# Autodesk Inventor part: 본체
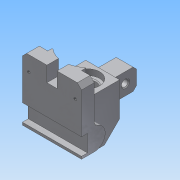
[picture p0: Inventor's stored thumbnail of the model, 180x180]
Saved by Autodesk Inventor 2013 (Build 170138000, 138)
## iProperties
Created: 2016-11
Part Number: 본체
Material: 알루미늄 6061
Document SubType Name: Modeling
Designer: Administrator
Density: 2.71 g/cm^3
Mass: 470.387 g
Surface Area: 316.229 cm^2
Volume: 173.574 cm^3
Author: Administrator
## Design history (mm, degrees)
sketch "스케치4"
  geometry: L1 (18, -11)-(0, -29); L2 (0, -29)-(-26, -29); L3 (-30, -25)-(-30, 29); L4 (-30, 29)-(18, 29); L5 (18, 29)-(18, -11); L6 (0, -29)-(0, 29); L7 (-26, -29)-(-30, -25); 3 further points
  constraints: 14 end point, 3 point on line, 2 vertical, 1 coincident, 1 horizontal, 1 midpoint, 1 parallel, 1 perpendicular
  dimensions: "d4" = 45 deg angle of L2 L1; "d5" = 58 distance between parallel lines of L2 L4; "d6" = 48 distance between parallel lines of L3 L5; "d8" = 30 distance from line of L3 L1.end; "d9" = 4 distance of L2.end point (-30, -29); "d10" = 4 distance of L3.start point (-30, -29) (= d9)
extrude "돌출1" new body sketch "스케치4" stored distance "d11" = 40; taper "d12" = 0 deg
sketch "스케치5"
  geometry: L1 (18, 29)-(18, -11) reference; L2 (18, -11)-(0, -29) reference; L3 (0, -29)-(-26, -29) reference; L4 (-26, -29)-(-30, -25) reference; L5 (-30, -25)-(-30, 29) reference; L6 (-30, 29)-(18, 29) reference; L7 (-27, -15)-(-42, -15); L8 (-42, 61)-(-27, 61); L9 (-27, 15.292)-(-27, 61); L10 (-35, -12)-(-42, -12); L11 (-35, -12)-(-35, 8); L12 (-35, 8)-(-42, 8); L13 (-42, -15)-(-42, -12); L14 (-42, 8)-(-42, 61); A1 r 13 centre (-27, -2) between (-27, -15) and (-23.389, 10.488); A2 r 5 centre (-22, 15.292) between (-27, 15.292) and (-23.389, 10.488); 2 further points
  constraints: 16 end point, 5 point on circle, 4 perpendicular, 3 point on line, 3 tangent, 2 centre point, 2 parallel, 1 horizontal
  dimensions: "d19" = 90 distance between parallel lines of L8 L3; "d21" = 26 diameter of A1; "d22" = 63 distance from line of L8 A1.centre; "d23" = 3 distance between parallel lines of L7 L10; "d25" = 20 distance of L10.start L11.end; "d26" = 60 distance between parallel lines of L1 L14; "d27" = 15 distance between parallel lines of L14 L9; "d28" = 7 distance between parallel lines of L13 L11; "d29" = 5 radius of A2
extrude "돌출2" join sketch "스케치5" stored distance "d30" = 70; taper "d31" = 0 deg
sketch "스케치6"
  geometry: L1 (0, -45)-(40, -45) reference; L2 (0, -45)-(0, 0) reference; L3 (0, -40)-(40, -40); L4 (40, -40)-(40, -45); L5 (40, -45)-(0, -45); L6 (0, -45)-(0, -40); 2 further points
  constraints: 8 end point, 2 midpoint, 2 parallel, 1 collinear, 1 horizontal, 1 perpendicular
  dimensions: "d32" = 5 distance of L5.end L3.start
extrude "돌출3" join sketch "스케치6" stored distance "d34" = 10; taper "d35" = 0 deg
sketch "스케치7"
  geometry: L1 (0, 0)-(70, 0) reference; L2 (0, 0)-(0, 15) reference; L3 (0, 15)-(15, 15) reference; L4 (15, 15)-(15, 20) reference; L5 (15, 20)-(55, 20) reference; L6 (55, 20)-(55, 15) reference; L7 (55, 15)-(70, 15) reference; L8 (70, 15)-(70, 0) reference; L9 (70, 0)-(0, 0) reference; C1 r 29 at (35, 42); 2 further points
  constraints: 1 centre point, 1 midpoint, 1 vertical alignment
  dimensions: "d36" = 58 diameter of C1; "d37" = 42 distance from line of L1 C1.centre
extrude "돌출4" cut sketch "스케치7" distance "d38" = 18; taper "d39" = 0 deg
sketch "스케치8"
  geometry: L1 (0, -29)-(-26, -29) reference; L2 (-26, -29)-(-30, -25) reference; L3 (-30, -25)-(-30, -15) reference; L4 (-30, -15)-(-42, -15) reference; L5 (-42, -15)-(-42, -12) reference; L6 (-42, -12)-(-35, -12) reference; L7 (-35, -12)-(-35, 8) reference; L8 (-35, 8)-(-42, 8) reference; L9 (-42, 8)-(-42, 61) reference; L10 (-42, 61)-(-29, 61) reference; L11 (-29, 61)-(-29, 43) reference; L12 (-29, 43)-(-22, 43) reference; L13 (-22, 43)-(-22, 29) reference; L14 (-22, 29)-(18, 29) reference; L15 (18, 29)-(18, -11) reference; L16 (18, -11)-(0, -29) reference; L17 (18, 24)-(44, 24); L18 (48, 20)-(48, 3); L19 (44, -1)-(18, -1); L20 (44, 24)-(48, 20); L21 (48, 3)-(44, -1); 3 further points
  constraints: 10 end point, 6 point on line, 1 horizontal, 1 parallel, 1 perpendicular
  dimensions: "d40" = 25 distance between parallel lines of L19 L17; "d42" = 5 distance between parallel lines of L17 L14; "d43" = 4 distance of L17.end point (48, 24); "d44" = 4 distance of L18.start point (48, 24) (= d43); "d45" = 4 distance of L18.end point (48, -1) (= d43); "d46" = 4 distance of L19.start point (48, -1) (= d45); "d47" = 90 distance between parallel lines of L18 L9
extrude "돌출5" join sketch "스케치8" stored distance "d48" = 20; taper "d49" = 0 deg
sketch "스케치9"
  geometry: L1 (-24, 44)-(-24, 18) reference; L2 (-61, -42)-(-8, -42) reference; 2 further points
  dimensions: "d50" = 12.5 distance from line of point (-11.5, 35) L1; "d51" = 77 distance from line of L2 point (-11.5, 35)
hole "구멍1" sketch "스케치9" at (-11.5, 35) diameter "d52" = 8; stored, may be unused: countersink angle "d56" = 90 deg, drill point angle "d58" = 118 deg; dims "d53" = 6, "d54" = 4, "d55" = 2, "d57" = 8
sketch "스케치12"
  geometry: 2 further points
  constraints: 1 coincident
hole "구멍2" sketch "스케치12" at (20, -18) diameter "d60" = 20; stored, may be unused: countersink angle "d64" = 90 deg, drill point angle "d66" = 118 deg; dims "d61" = 6, "d62" = 29, "d63" = 7, "d65" = 8
chamfer "모따기1" distance "d67" = 1; stored, may be unused: second distance "d68" = 2, angle "d69" = 45 deg
sketch "스케치13"
  geometry: L1 (0, 0)-(15, 0) reference; L2 (15, 45.708)-(15, 0) reference; L3 (15, 0)-(0, 0) reference; L4 (0, 0)-(-9.417, 0) reference; L5 (-9.417, 0)-(-9.417, 18) reference; L6 (-9.417, 18)-(-30.583, 18) reference; L7 (-30.583, 18)-(-30.583, 0) reference; L8 (-30.583, 0)-(-40, 0) reference; L9 (-40, 0)-(-55, 0) reference; L10 (-55, 0)-(-55, 45.708) reference; L11 (-55, 45.708)-(-55, 76) reference; L12 (-55, 76)-(-40, 76) reference; L13 (-40, 76)-(-40, 89) reference; L14 (-40, 89)-(0, 89) reference; L15 (0, 89)-(0, 76) reference; L16 (0, 76)-(15, 76) reference; L17 (15, 76)-(15, 45.708) reference; L18 (15, 45.708)-(15, 0) reference; L19 (0, 45.708)-(0, 0) reference; L20 (15, 45.708)-(0, 45.708) reference; L21 (-40, 0)-(-40, 45.708) reference; L22 (-40, 45.708)-(-55, 45.708) reference; 3 further points
  dimensions: "d70" = 18 distance from line of L1 point (7.5, 18); "d71" = 18 distance from line of L9 point (-47.5, 18); "d76" = 7.5 distance from line of L10 point (-47.5, 18); "d77" = 7.5 distance from line of L2 point (7.5, 18)
hole "구멍3" sketch "스케치13" at (7.5, 18), (-47.5, 18) diameter "d78" = 3.242; stored, may be unused: countersink angle "d82" = 90 deg, drill point angle "d84" = 118 deg; dims "d79" = 6, "d80" = 29, "d81" = 7, "d83" = 8
chamfer "모따기2" distance "d85" = 5; stored, may be unused: second distance "d86" = 2, angle "d87" = 45 deg
fillet "모깎기1" dims "d88" = 3
sketch "스케치14"
  geometry: L1 (29, -22)-(29, 18) reference; L2 (29, 18)-(-11, 18) reference; 2 further points
  constraints: 1 other
  dimensions: "d89" = 25 distance from line of point (4, 0) L1; "d90" = 18 distance from line of point (4, 0) L2
feature "엠보싱1" sketch "스케치14" dims "d4" = 45 deg, "d5" = 58, "d6" = 48, "d8" = 30, "d9" = 4, "d10" = 4 (= d9), "d91" = 0.5, "d92" = 0
sketch "스케치15"
  geometry: L1 (-50, -15)-(10, -15) reference; L2 (-26, 6.98)-(-14, 6.98); L3 (-14, 6.98)-(-14, -15); L4 (-14, -15)-(-26, -15); L5 (-26, -15)-(-26, 6.98); 1 further point
  constraints: 8 end point, 2 midpoint, 2 parallel, 1 horizontal, 1 perpendicular
  dimensions: "d93" = 12 distance between parallel lines of L3 L5
extrude "돌출6" cut sketch "스케치15" stored distance "d95" = 20; taper "d96" = 0 deg
node "솔리드1"
node "절단 모서리 투영1"
node "절단 모서리 투영2"
node "절단 모서리 투영3"
node "절단 모서리 투영5"
other parameters: "d14" = 15
